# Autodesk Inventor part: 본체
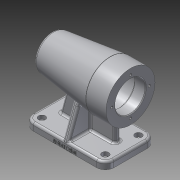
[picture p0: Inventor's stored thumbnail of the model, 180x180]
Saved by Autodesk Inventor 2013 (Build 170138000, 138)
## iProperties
Created: 2018-09
Part Number: 본체
Material: 알루미늄 6061
Document SubType Name: Modeling
Designer: Administrator
Density: 2.71 g/cm^3
Mass: 734.876 g
Surface Area: 664.558 cm^2
Volume: 271.172 cm^3
Author: Administrator
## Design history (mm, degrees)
sketch "스케치1"
  geometry: L1 (0, 0)-(0, 34); L2 (0, 34)-(-28, 34); L3 (-28, 34)-(-108.27, 24.144); L4 (-112, 0)-(0, 0); A1 r 80 centre (-32, 0) between (-108.27, 24.144) and (-112, 0); 1 further point
  constraints: 8 end point, 2 point on circle, 1 centre point, 1 coincident, 1 horizontal alignment, 1 perpendicular, 1 vertical
  dimensions: "d0" = 68 diameter of L2 L4; "d3" = 28 distance of L1.end L2.end; "d4" = 7 deg angle of L2 L3; "d5" = 160 diameter of A1; "d6" = 112 distance from line of L1 L4.start
revolve "회전1" sketch "스케치1" stored, may be unused: angle "d7" = 90 deg
hole "구멍1" diameter "d10" = 42; stored, may be unused: countersink angle "d14" = 90 deg, drill point angle "d16" = 0 deg; dims "d11" = 6, "d12" = 4, "d13" = 2, "d15" = 15, "d17" = 10, "d18" = 10
sketch "스케치2"
  geometry: C1 r 21 at (0, 0) reference; C2 r 24 at (0, 0)
  constraints: 1 centre point, 1 coincident
  dimensions: "d19" = 48 diameter of C2
extrude "돌출1" cut sketch "스케치2" distance "d21" = 54; taper "d22" = 0 deg
hole "구멍2" diameter "d25" = 42; stored, may be unused: countersink angle "d29" = 90 deg, drill point angle "d31" = 0 deg; dims "d26" = 6, "d27" = 4, "d28" = 2, "d30" = 12, "d32" = 10, "d33" = 10
hole "구멍3" diameter "d36" = 35; stored, may be unused: countersink angle "d40" = 90 deg, drill point angle "d42" = 0 deg; dims "d37" = 6, "d38" = 4, "d39" = 2, "d41" = 18, "d43" = 10, "d44" = 10
hole "구멍4" diameter "d47" = 32; stored, may be unused: countersink angle "d51" = 90 deg, drill point angle "d53" = 0 deg; dims "d48" = 6, "d49" = 4, "d50" = 2, "d52" = 4, "d54" = 10, "d55" = 10
hole "구멍5" diameter "d58" = 21; stored, may be unused: countersink angle "d62" = 90 deg, drill point angle "d64" = 0 deg; dims "d56" = 10, "d57" = 10, "d59" = 6, "d60" = 4, "d61" = 2, "d63" = 3
fillet "모깎기1" dims "d65" = 3
fillet "모깎기2" dims "d66" = 0.3
chamfer "모따기1" distance "d67" = 1; stored, may be unused: second distance "d68" = 2, angle "d69" = 45 deg
sketch "스케치3"
  geometry: C1 r 34 at (0, 0) reference; 1 further point
  constraints: 1 vertical alignment
  dimensions: "d70" = 26 distance of C1.centre point (0, 26)
hole "구멍6" sketch "스케치3" at (0, 26) diameter "d71" = 3.242; stored, may be unused: countersink angle "d75" = 90 deg, drill point angle "d77" = 118 deg; dims "d72" = 8, "d73" = 4, "d74" = 2, "d76" = 11
node "작업 평면1"
sketch "스케치4"
  geometry: L1 (-112, -35)-(0, -35); L2 (0, -35)-(0, 35); L3 (0, 35)-(-112, 35); L4 (-112, 35)-(-112, -35); 2 further points
  constraints: 8 end point, 2 coincident, 2 parallel, 1 horizontal, 1 midpoint, 1 perpendicular
  dimensions: "d82" = 70 distance of L1.end L2.end; "d84" = 112 distance of L2.end L3.end
extrude "돌출2" join sketch "스케치4" distance "d85" = 10; taper "d86" = 0 deg
fillet "모깎기3" dims "d87" = 12
node "작업 평면2"
node "작업 평면3"
sketch "스케치11"
  geometry: L1 (0, -23)-(0, 23) reference; L2 (-100, 35)-(-12, 35) reference; L3 (-112, -23)-(-112, 23) reference; L4 (0, 23)-(0, -23) reference; L5 (-12, -35)-(-100, -35) reference; L6 (-52, 4)-(-18, 4); L7 (-18, 4)-(-18, -4); L8 (-18, -4)-(-52, -4); L9 (-52, -4)-(-52, 4); A1 r 12 centre (-100, 23) between (-100, 35) and (-112, 23) reference; A2 r 12 centre (-100, -23) between (-112, -23) and (-100, -35) reference; A3 r 12 centre (-12, 23) between (0, 23) and (-12, 35) reference; A4 r 12 centre (-12, -23) between (-12, -35) and (0, -23) reference; 3 further points
  constraints: 8 end point, 2 parallel, 1 horizontal, 1 horizontal alignment, 1 midpoint, 1 perpendicular
  dimensions: "d128" = 18 distance between parallel lines of L1 L7; "d129" = 8 distance of L6.end L7.end
extrude "돌출6" join sketch "스케치11" stored distance "d130" = 8; taper "d131" = 0 deg
sketch "스케치12"
  geometry: A1 r 12 centre (-100, 23) between (-100, 35) and (-112, 23) reference; A2 r 12 centre (-100, -23) between (-112, -23) and (-100, -35) reference; 3 further points
  constraints: 2 coincident
hole "구멍8" sketch "스케치12" at (-100, 23), (-100, -23) diameter "d132" = 5.5; stored, may be unused: countersink angle "d136" = 90 deg, drill point angle "d138" = 118 deg; dims "d133" = 8, "d134" = 9.5, "d135" = 5.4, "d137" = 11
sketch "스케치13"
  geometry: A1 r 12 centre (-12, -23) between (-12, -35) and (0, -23) reference; A2 r 12 centre (-12, 23) between (0, 23) and (-12, 35) reference; 3 further points
  constraints: 2 coincident
hole "구멍9" sketch "스케치13" at (-12, 23), (-12, -23) diameter "d139" = 5.5; stored, may be unused: countersink angle "d143" = 90 deg, drill point angle "d145" = 118 deg; dims "d140" = 8, "d141" = 9.5, "d142" = 5.4, "d144" = 11
sketch "스케치14"
  geometry: L1 (0, 0)-(88, 0) reference; L2 (100, 0)-(100, 10) reference; 3 further points
  constraints: 1 other
  dimensions: "d153" = 3 distance from line of L1 point (44, 3); "d155" = 56 distance from line of L2 point (44, 3)
feature "엠보싱1" sketch "스케치14" dims "d149" = 0.5, "d150" = 0
fillet "모깎기10" dims "d151" = 3
fillet "모깎기11" dims "d152" = 3
fillet "모깎기12" dims "d156" = 3
node "작업 평면4"
sketch "스케치15"
  geometry: L1 (-35, -69.423)-(-35.5, -69.423) reference; L2 (-35.5, -69.423)-(-35.5, -69.092) reference; L3 (-35.5, -69.092)-(-35, -69.092) reference; L4 (-35, -69.092)-(-35, -67) reference; L5 (-32, -64)-(32, -64) reference; L6 (35, -67)-(35, -74) reference; L7 (35, -74)-(-35, -74) reference; L8 (-35, -74)-(-35, -69.423) reference; L9 (-34.819, -65.974)-(-16.98, -16.961); L10 (16.976, -16.951)-(34.819, -65.974); L11 (-35, -69.423)-(-35.5, -69.423) reference; L12 (-35.5, -69.423)-(-35.5, -69.092) reference; L13 (-35.5, -69.092)-(-35, -69.092) reference; L14 (-35, -69.092)-(-35, -67) reference; L15 (-32, -64)-(32, -64) reference; L16 (35, -67)-(35, -74) reference; L17 (35, -74)-(-35, -74) reference; L18 (-35, -74)-(-35, -69.423) reference; L19 (-35, -69.423)-(-35.5, -69.423) reference; L20 (-35.5, -69.423)-(-35.5, -69.092) reference; L21 (-35.5, -69.092)-(-35, -69.092) reference; L22 (-35, -69.092)-(-35, -67) reference; L23 (-32, -64)-(32, -64) reference; L24 (35, -67)-(35, -74) reference; L25 (35, -74)-(-35, -74) reference; L26 (-35, -74)-(-35, -69.423) reference; L27 (-35, -69.423)-(-35.5, -69.423) reference; L28 (-35.5, -69.423)-(-35.5, -69.092) reference; L29 (-35.5, -69.092)-(-35, -69.092) reference; L30 (-35, -69.092)-(-35, -67) reference; L31 (-32, -64)-(32, -64) reference; L32 (35, -67)-(35, -74) reference; L33 (35, -74)-(-35, -74) reference; L34 (-35, -74)-(-35, -69.423) reference; L35 (-35, -69.423)-(-35.5, -69.423) reference; L36 (-35.5, -69.423)-(-35.5, -69.092) reference; L37 (-35.5, -69.092)-(-35, -69.092) reference; L38 (-35, -69.092)-(-35, -67) reference; L39 (-32, -64)-(32, -64) reference; L40 (35, -67)-(35, -74) reference; L41 (35, -74)-(-35, -74) reference; L42 (-35, -74)-(-35, -69.423) reference; L43 (23, -67)-(-23, -67) reference; L44 (-34.819, -65.974)-(34.819, -65.974); C1 r 30.562 at (0, 0) reference; C2 r 30.562 at (0, 0) reference; C3 r 24 at (0, 0) reference; C4 r 24 at (0, 0) reference; C5 r 30.562 at (0, 0) reference; C6 r 24 at (0, 0) reference; C7 r 30.562 at (0, 0) reference; C8 r 24 at (0, 0) reference; C9 r 30.562 at (0, 0) reference; C10 r 24 at (0, 0) reference; A1 r 3 centre (-32, -67) between (-32, -64) and (-35, -67) reference; A2 r 3 centre (32, -67) between (35, -67) and (32, -64) reference; A3 r 3 centre (-32, -67) between (-32, -64) and (-35, -67) reference; A4 r 3 centre (32, -67) between (35, -67) and (32, -64) reference; A5 r 3 centre (-32, -67) between (-32, -64) and (-35, -67) reference; A6 r 3 centre (32, -67) between (35, -67) and (32, -64) reference; A7 r 3 centre (-32, -67) between (-32, -64) and (-35, -67) reference; A8 r 3 centre (32, -67) between (35, -67) and (32, -64) reference; A9 r 3 centre (-32, -67) between (-32, -64) and (-35, -67) reference; A10 r 3 centre (32, -67) between (35, -67) and (32, -64) reference; A11 r 24 centre (0, 0) between (-16.98, -16.961) and (16.98, -16.961); 2 further points
  constraints: 6 end point, 4 point on circle, 2 tangent, 1 centre point, 1 coincident, 1 point on line, 2 other
  dimensions: "d158" = 20 deg angle of L6 L10; "d159" = 20 deg angle of L8 L9
extrude "돌출7" join sketch "스케치15" stored distance "d160" = 8; taper "d161" = 0 deg
sketch "스케치16"
  geometry: L1 (99, -17.2)-(99, -16) reference; L2 (99, -16)-(102.7, -16) reference; L3 (103, -15.7)-(103, -10.5) reference; L4 (106, -7.5)-(106, 7.5) reference; L5 (103, 10.5)-(103, 15.7) reference; L6 (102.7, 16)-(99, 16) reference; L7 (99, 16)-(99, 17.2) reference; L8 (98.7, 17.5)-(81, 17.5) reference; L9 (81, 17.5)-(81, 20.7) reference; L10 (80.7, 21)-(69, 21) reference; L11 (66, 24)-(18, 24) reference; L12 (15, 21)-(1, 21) reference; L13 (1, 21)-(0, 22) reference; L14 (0, 22)-(0, 24.379) reference; L15 (0, 24.379)-(11, 24.379) reference; L16 (11, 24.379)-(11.974, 26) reference; L17 (11.974, 26)-(11, 27.621) reference; L18 (11, 27.621)-(0, 27.621) reference; L19 (0, 27.621)-(0, 34) reference; L20 (0, 34)-(27.817, 34) reference; L21 (28.182, 33.978)-(106.331, 24.382) reference; L22 (106.331, -24.382)-(60, -30.071) reference; L23 (60, -30.071)-(60, -64) reference; L24 (60, -64)-(109, -64) reference; L25 (112, -67)-(112, -74) reference; L26 (112, -74)-(0, -74) reference; L27 (0, -74)-(0, -67) reference; L28 (3, -64)-(18, -64) reference; L29 (18, -64)-(18, -37) reference; L30 (15, -34)-(0, -34) reference; L31 (0, -34)-(0, -27.621) reference; L32 (0, -27.621)-(11, -27.621) reference; L33 (11, -27.621)-(11.974, -26) reference; L34 (11.974, -26)-(11, -24.379) reference; L35 (11, -24.379)-(0, -24.379) reference; L36 (0, -24.379)-(0, -22) reference; L37 (0, -22)-(1, -21) reference; L38 (1, -21)-(15, -21) reference; L39 (18, -24)-(66, -24) reference; L40 (69, -21)-(80.7, -21) reference; L41 (81, -20.7)-(81, -17.5) reference; L42 (81, -17.5)-(98.7, -17.5) reference; L43 (94, -64)-(82.905, -22.595); A1 r 0.3 centre (98.7, -17.2) between (98.7, -17.5) and (99, -17.2) reference; A2 r 0.3 centre (102.7, -15.7) between (102.7, -16) and (103, -15.7) reference; A3 r 3 centre (103, -7.5) between (103, -10.5) and (106, -7.5) reference; A4 r 3 centre (103, 7.5) between (106, 7.5) and (103, 10.5) reference; A5 r 0.3 centre (102.7, 15.7) between (103, 15.7) and (102.7, 16) reference; A6 r 0.3 centre (98.7, 17.2) between (99, 17.2) and (98.7, 17.5) reference; A7 r 0.3 centre (80.7, 20.7) between (81, 20.7) and (80.7, 21) reference; A8 r 3 centre (66, 21) between (69, 21) and (66, 24) reference; A9 r 3 centre (18, 21) between (18, 24) and (15, 21) reference; A10 r 3 centre (27.817, 31) between (28.182, 33.978) and (27.817, 34) reference; A11 r 3 centre (105.965, 21.405) between (108.847, 22.238) and (106.331, 24.382) reference; A12 r 80 centre (32, 0) between (108.847, -22.238) and (108.847, 22.238) reference; A13 r 3 centre (105.965, -21.405) between (106.331, -24.382) and (108.847, -22.238) reference; A14 r 3 centre (109, -67) between (112, -67) and (109, -64) reference; A15 r 3 centre (3, -67) between (3, -64) and (0, -67) reference; A16 r 3 centre (15, -37) between (18, -37) and (15, -34) reference; A17 r 3 centre (18, -21) between (15, -21) and (18, -24) reference; A18 r 3 centre (66, -21) between (66, -24) and (69, -21) reference; A19 r 0.3 centre (80.7, -20.7) between (80.7, -21) and (81, -20.7) reference; 1 further point
  constraints: 2 end point, 1 point on line
  dimensions: "d162" = 18 distance from line of L25 L43.start; "d163" = 105 deg angle of L24 L43
feature "리브3" sketch "스케치16" dims "d164" = 1, "d165" = 8, "d166" = 0, "d167" = 0, "d168" = 1, "d169" = 1
fillet "모깎기13" dims "d170" = 3
fillet "모깎기14" dims "d171" = 3
fillet "모깎기15" dims "d172" = 3
node "솔리드1"
pattern_circular "원형 패턴1" dims angle "d79" = 360 deg
node "절단 모서리 투영5"
node "절단 모서리 투영6"
node "절단 모서리 투영7"
node "절단 모서리 투영8"
node "절단 모서리 투영9"
node "절단 모서리 투영10"
node "절단 모서리 투영11"
other parameters: "d81" = -74, "d96" = -56, "d115" = -56, "d157" = -56
